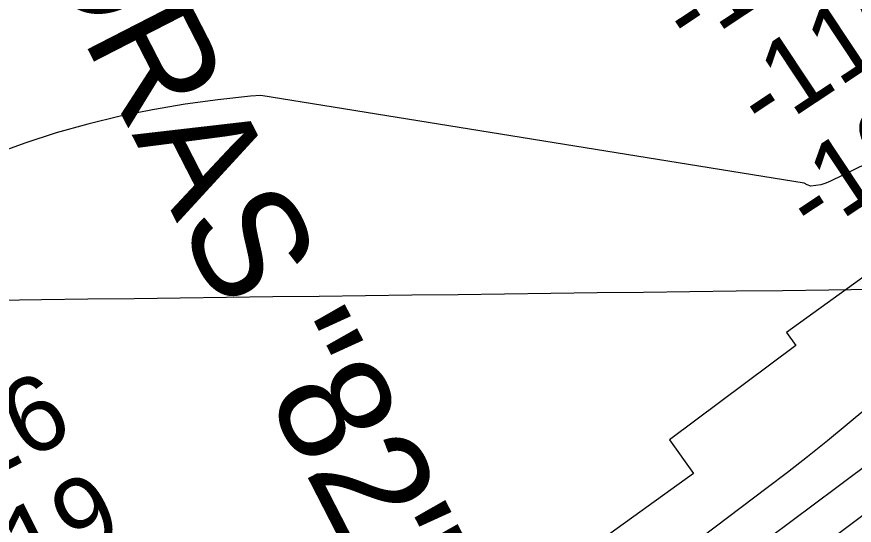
# Model space of a CAD drawing. Extents: x 3715084 to 3753216, y 488173 to 513963.
# Drawn here: x 3731429 to 3732175, y 499599 to 500052 of the extents above; entities that cross this region are included whole.
import ezdxf

# ---------------------------------------------------------------- set-up
doc = ezdxf.new("R2010")
doc.units = 0
for name, color, linetype in [('V-CHAN-NAID', 7, 'Continuous'), ('V-GRID-MAJR', 7, 'Continuous'), ('V-RIVR-RANG', 7, 'Continuous'), ('V-RRAP-RVMT', 7, 'Continuous'), ('V-TOPO-MAJR', 7, 'Continuous'), ('V-TOPO-MINR', 7, 'Continuous')]:
    doc.layers.add(name, color=color, linetype=linetype)

msp = doc.modelspace()

# ---------------------------------------------------------------- linework, layer by layer
at = {"layer": 'V-GRID-MAJR'}
msp.add_spline([(3719277.161, 499651.167), (3724559.356, 499715.322), (3729841.541, 499780.245), (3735123.717, 499845.93700000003), (3740405.883, 499912.396), (3745688.039, 499979.624), (3750970.185, 500047.621), (3750970.186, 500047.621)], degree=3, dxfattribs=at)
at = {"layer": 'V-RRAP-RVMT'}
for p, q in [((3732228.9630000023, 499853.10100000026), (3732114.7270000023, 499770.75400000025)), ((3732114.7270000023, 499770.75400000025), (3732123.0230000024, 499759.07000000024)), ((3732123.0230000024, 499759.07000000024), (3732010.6260000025, 499674.9850000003)), ((3732010.6260000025, 499674.9850000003), (3732032.0620000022, 499644.8760000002)), ((3732032.0620000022, 499644.8760000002), (3731798.0060000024, 499476.8490000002))]:
    msp.add_line(p, q, dxfattribs=at)
at = {"layer": 'V-TOPO-MAJR'}
msp.add_lwpolyline([(3732000.377158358, 499513.7854435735), (3732080.0657900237, 499573.2930916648), (3732159.724481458, 499632.84086528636), (3732304.494029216, 499741.14659879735), (3732311.7309979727, 499746.5906216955), (3732318.948643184, 499752.06000541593), (3732326.137303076, 499757.5674303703), (3732333.3066394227, 499763.1002161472), (3732535.7316609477, 499920.1721206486), (3732614.131475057, 499981.74255253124), (3732692.0442290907, 500043.91609410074), (3732769.2263930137, 500106.9943002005)], dxfattribs=at)
at = {"layer": 'V-TOPO-MINR'}
for points in [[(3732202.1933752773, 499929.22270173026), (3732199.5317895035, 499927.6287389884), (3732196.784493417, 499926.1662987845), (3732153.883937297, 499905.38329725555), (3732149.703820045, 499903.68248343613), (3732145.433626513, 499902.3541664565), (3732141.0283185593, 499901.5845947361), (3732136.532934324, 499901.18751985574), (3732133.139352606, 499902.1224831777), (3732130.563708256, 499903.7845343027), (3731646.510191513, 499982.00034866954), (3731637.4072782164, 499981.1912011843), (3731608.1107387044, 499978.02183377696), (3731578.9279324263, 499974.11147322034), (3731549.9157260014, 499969.0896229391), (3731521.0172528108, 499963.3267795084), (3731492.404241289, 499956.34558011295), (3731464.056386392, 499948.4878381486), (3731436.1062664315, 499939.31528233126), (3731408.4213030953, 499929.26618394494)], [(3731418.6115811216, 499185.9903395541), (3731539.3417904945, 499250.53052315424), (3731557.2961822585, 499260.39148691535), (3731575.0947494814, 499270.51922923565), (3731592.6595798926, 499281.0471393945), (3731610.0685857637, 499291.8418281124), (3731709.6843329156, 499355.18188153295), (3731776.231841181, 499398.6424204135), (3731842.043873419, 499443.1621750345), (3731906.7526916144, 499489.27075326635), (3731970.726033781, 499536.43854723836), (3732097.5584063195, 499632.35789194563), (3732115.595816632, 499646.2020661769), (3732133.498951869, 499660.21529411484), (3732151.200674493, 499674.48210261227), (3732168.7681220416, 499688.9179648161), (3732186.2520773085, 499703.4598055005)], [(3731422.704916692, 499053.57361793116), (3731472.7660384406, 499084.0579859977), (3731522.503361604, 499115.08388729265), (3731584.5499506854, 499154.4877315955), (3731602.8503376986, 499166.46170375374), (3731620.923584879, 499178.75991888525), (3731638.656122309, 499191.5444984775), (3731656.161519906, 499204.653321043), (3731708.9670352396, 499245.32776867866), (3731745.2860989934, 499273.41608654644), (3731781.531796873, 499301.59838314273), (3731817.6674459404, 499329.9216478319), (3731853.729729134, 499358.3388912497), (3731889.8512083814, 499386.6781433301), (3731926.1249606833, 499414.8194554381), (3731962.6271225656, 499442.6638575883), (3731999.281557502, 499470.3103197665), (3732059.023132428, 499514.98894035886), (3732105.472857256, 499549.7672732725), (3732151.896798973, 499584.5799491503), (3732198.2820660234, 499619.44413947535)]]:
    msp.add_lwpolyline(points, dxfattribs=at)

# ---------------------------------------------------------------- texts
at = {"layer": 'V-CHAN-NAID'}
msp.add_text('POYDRAS "82" (81.6)', height=100.00000199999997, rotation=297.16950570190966, dxfattribs=at).set_placement((3731314.1228443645, 500370.0896584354))
at = {"layer": 'V-RIVR-RANG'}
for s, height, rotation, p in [('-109', 67.00000000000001, 33.53019444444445, (3732028.6926875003, 500021.00997690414)), ('-110', 67.00000000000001, 33.53019444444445, (3732095.1577206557, 499945.0906668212)), ('-109', 67.00000000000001, 33.53019444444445, (3732138.7546875, 499854.01897690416)), ('-116', 66.99999999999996, 26.73205555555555, (3731321.785146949, 499598.32363257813)), ('-119', 66.99999999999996, 26.73205555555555, (3731366.7817336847, 499509.01928555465))]:
    msp.add_text(s, height=height, rotation=rotation, dxfattribs=at).set_placement(p)

doc.saveas('drawing.dxf')
